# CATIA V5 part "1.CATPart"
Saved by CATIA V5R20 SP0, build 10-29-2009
Part number: bati
Bounding box of the stored display mesh (mm): x -60 to 2.5, y -130 to 300, z 0 to 370
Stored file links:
  C:\Users\Willy\Documents\ThinkMotion\1691\1.CATPart
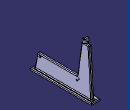
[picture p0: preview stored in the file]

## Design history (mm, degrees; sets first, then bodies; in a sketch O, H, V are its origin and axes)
Body1 (main body)
  Sketch1 on xy-plane, origin (0, 0, 0), H (1, 0, 0), V (0, 1, 0)
    line L1 (-60, 300) -> (0, 300)
    line L2 (0, 300) -> (0, -130)
    line L3 (0, -130) -> (-60, -130)
    line L4 (-60, -130) -> (-60, 300)
    distance L4 L2 = 60
    distance L3 L1 = 430
    horizontal: L1 H, L3 H
    vertical: L2 V, L4 V
  Pad1: profile Sketch1, direction (0, 0, 1), length 15
  Sketch2 on face of Pad1 from Sketch1.L2, origin (0, 0, 0), H (0, 1, 0), V (0, 0, 1)
    point P1 (-115, 15)
    line L1 (-115, 15) -> (-95, 115)
    line L2 (-95, 115) -> (185, 115)
    line L3 (185, 115) -> (215, 335)
    line L4 (215, 335) -> (265, 335)
    line L5 (265, 335) -> (285, 15)
    point P6 (285, 15)
    line L6 (285, 15) -> (-115, 15)
    reference projected line E1 (-130, 15) -> (300, 15) from edge [face of Pad1 from Sketch1.L2 | end face of Pad1]
    reference projected line E2 (300, 0) -> (300, 15) from edge [face of Pad1 from Sketch1.L1 | face of Pad1 from Sketch1.L2]
    reference projected line E3 (-130, 0) -> (-130, 15) from edge [face of Pad1 from Sketch1.L2 | face of Pad1 from Sketch1.L3]
    circle A1 centre (-74.1166, 104.5809) radius 5
    point P7 (-74.1166, 104.5809)
    circle A2 centre (195.8778, 102.8297) radius 5
    point P8 (195.8778, 102.8297)
    distance P6 E2 = 15
    distance P1 E3 = 15
    radius A1 = 5
    radius A2 = 5
    distance P8 P7 = 270
    horizontal: L2 H, L4 H, L6 H
    coincidence: L6 E1
  Pad2: profile Sketch2, direction (-1, 0, 0), length 35, opposite side length -15
  DatumCurve1 to DatumCurve3
  Sketch3 on face of Pad2 from Sketch2.L4, origin (0, 0, 335), H (1, 0, 0), V (0, 1, 0)
    circle A1 centre (-7.5, 240) radius 5
    point P1 (-7.5, 240)
    circle A2 centre (-7.5, 240) radius 10
    reference projected line E1 (-15, 215) -> (-35, 215) from edge [face of Pad2 from Sketch2.L4 | face of Pad2 from Sketch2.L3]
    reference projected line E2 (-15, 265) -> (-35, 265) from edge [face of Pad2 from Sketch2.L5 | face of Pad2 from Sketch2.L4]
    reference projected line E3 (-15, 265) -> (-15, 215) from edge [face of Pad2 from Sketch2.L4 | start face of Pad2]
    radius A2 = 10
    distance P1 E3 = 7.5
    radius A1 = 5
    equidistance: E1 E2 P1
  Pad3: profile Sketch3, direction (0, 0, 1), length 35, opposite side length -15
  Sketch4 on end face of Pad2, origin (-35, 0, 0), H (0, -1, 0), V (0, 0, 1)
    line L1 (-245, 370) -> (-235, 370)
    line L2 (-235, 370) -> (-235, 335)
    line L3 (-235, 335) -> (-245, 335)
    line L4 (-245, 335) -> (-245, 370)
    reference projected line E1 through (-240, 0) direction (0, 1) from axis of face of Pad3 from Sketch3.A2
    reference projected line E2 (-265, 335) -> (-215, 335) from edge [end face of Pad2 | face of Pad2 from Sketch2.L4]
    reference projected line E3 (-250, 370) -> (-230, 370) from edge [face of Pad3 from Sketch3.A2 | end face of Pad3]
    length L1 = 10
    horizontal: L1 H, L3 H
    vertical: L2 V, L4 V
    symmetry: L4 L2 E1
    coincidence: L3 E2, E3 L1
  Pad4: profile Sketch4, direction (1, 0, 0), length 5
  Sketch5 on end face of Pad4, origin (-30, 0, 0), H (0, 1, 0), V (0, 0, 1)
    point P1 (235, 370)
    line L1 (235, 370) -> (245, 370)
    line L2 (245, 370) -> (245, 350)
    line L3 (245, 350) -> (235, 350)
    line L4 (235, 350) -> (235, 370)
    reference projected point E1 (235, 370) from vertex [end face of Pad4 | face of Pad4 from Sketch4.L2 | face of Pad4 from Sketch4.L1]
    reference projected line E2 (245, 370) -> (245, 335) from edge [end face of Pad4 | face of Pad4 from Sketch4.L4]
    reference projected line E3 (230, 350) -> (250, 350) from edge [start face of Pad3 | face of Pad3 from Sketch3.A2]
    horizontal: L1 H, L3 H
    vertical: L2 V, L4 V
    coincidence: P1 E1, E2 L2, E3 L3
  Pad5: profile Sketch5, direction (1, 0, 0), up to the existing solid (limit type 2)
  Sketch6 on face of Pad4, origin (-35, 0, 0), H (0, -1, 0), V (0, 0, 1)
    circle A1 centre (74.1166, 104.5809) radius 5
    reference projected circle E1 centre (74.1166, 104.5809) radius 5 from edge [face of Pad2 from Sketch2.A1 | end face of Pad2]
    coincidence: A1 E1
  Pad6: profile Sketch6, direction (1, 0, 0), length 25
  Sketch7 on face of Pad6, origin (-35, 0, 0), H (0, -1, 0), V (0, 0, 1)
    circle A1 centre (-195.8778, 102.8297) radius 5
    reference projected circle E1 centre (-195.8778, 102.8297) radius 5 from edge [face of Pad2 from Sketch2.A2 | end face of Pad2]
    coincidence: A1 E1
  Pad7: profile Sketch7, direction (1, 0, 0), length 35
  Fillet1: radius 5, on end face of Pad1; face of Pad2 from Sketch2.L1; face of Pad2 from Sketch2.L2; face of Pad2 from Sketch2.L3; face of Pad2 from Sketch2.L4; face of Pad2 from Sketch2.L5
